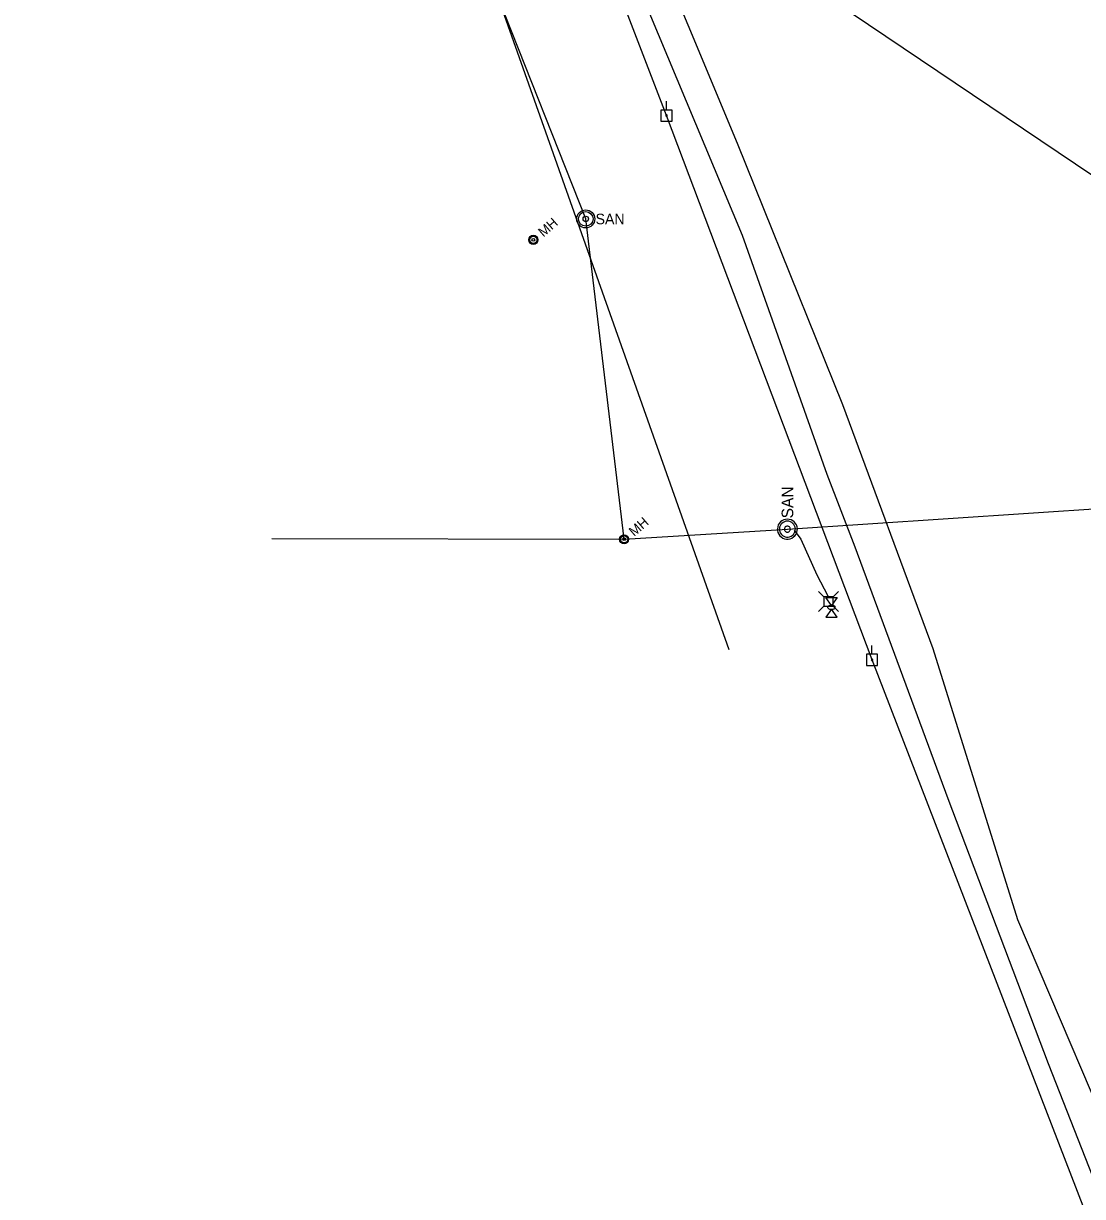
# Model space of a CAD drawing. Extents: x 596028 to 606371, y 330010 to 403088.
# Drawn here: x 602147.8 to 602498.3, y 353446.6 to 353834.8 of the extents above; entities that cross this region are included whole.
import ezdxf

# ---------------------------------------------------------------- set-up
doc = ezdxf.new("R2010")
doc.units = 0
for name, color, linetype in [('E_FTMS_Conduit', 7, 'Continuous'), ('E_UTL_E', 7, 'Continuous'), ('E_UTL_E_Bold', 7, 'Continuous'), ('E_UTL_E_UG', 7, 'Continuous'), ('E_UTL_EPowerPole', 7, 'Continuous'), ('E_UTL_FO_UG_QWEST', 7, 'Continuous'), ('E_UTL_G_UG', 7, 'Continuous'), ('E_UTL_Overhead', 7, 'Continuous'), ('E_UTL_SAN_MH', 7, 'Continuous'), ('E_UTL_SAN_UG', 7, 'Continuous'), ('E_UTL_SAN_UG_MMSD', 7, 'Continuous')]:
    doc.layers.add(name, color=color, linetype=linetype)

msp = doc.modelspace()

# ---------------------------------------------------------------- linework, layer by layer
at = {"layer": 'E_FTMS_Conduit'}
msp.add_lwpolyline([(602734.78, 352891.69), (602698.69, 352975.92), (602667.81, 353054.24), (602645.72, 353130.78), (602610.14, 353206.87), (602580.81, 353284.37), (602548.82, 353367.3), (602515.43, 353447.91), (602476.95, 353538.14), (602448.85, 353627.85), (602419.04, 353708.61), (602384.09, 353795.14), (602351.42, 353873.57), (602322.54, 353957.36), (602293.02, 354034.05), (602262.08, 354114.29), (602230.08, 354192.55), (602200.4, 354271.32)], dxfattribs=at)
at = {"layer": 'E_UTL_E'}
for points in [[(602412.72, 353645.06), (602410.97, 353646.82)], [(602415.81, 353645.06), (602417.57, 353646.82)], [(602415.81, 353645.06), (602412.72, 353645.06)], [(602412.72, 353645.06), (602412.72, 353641.97)], [(602415.81, 353641.97), (602415.81, 353645.06)], [(602412.72, 353641.97), (602410.97, 353640.22)], [(602412.72, 353641.97), (602415.81, 353641.97)], [(602415.81, 353641.97), (602417.57, 353640.22)]]:
    msp.add_lwpolyline(points, dxfattribs=at)
at = {"layer": 'E_UTL_E_Bold'}
for points in [[(602413.33, 353644.88), (602417.14, 353644.88)], [(602415.23, 353642.22), (602413.33, 353644.88)], [(602417.14, 353644.88), (602415.23, 353642.22)], [(602415.23, 353640.94), (602413.33, 353638.28)], [(602416.5, 353641.58), (602416.48, 353641.7), (602416.41, 353641.82), (602416.3, 353641.92), (602416.15, 353642.02), (602415.97, 353642.1), (602415.76, 353642.16), (602415.53, 353642.2), (602415.29, 353642.21), (602415.05, 353642.21), (602414.82, 353642.18), (602414.6, 353642.13), (602414.4, 353642.06), (602414.23, 353641.97), (602414.1, 353641.87), (602414.01, 353641.76), (602413.97, 353641.64), (602413.97, 353641.52), (602414.01, 353641.4), (602414.1, 353641.29), (602414.23, 353641.19), (602414.4, 353641.1), (602414.6, 353641.03), (602414.82, 353640.98), (602415.05, 353640.95), (602415.29, 353640.95), (602415.53, 353640.96), (602415.76, 353641), (602415.97, 353641.06), (602416.15, 353641.14), (602416.3, 353641.24), (602416.41, 353641.34), (602416.48, 353641.46), (602416.5, 353641.58)], [(602417.14, 353638.28), (602415.23, 353640.94)], [(602413.33, 353638.28), (602417.14, 353638.28)]]:
    msp.add_lwpolyline(points, dxfattribs=at)
at = {"layer": 'E_UTL_E_UG'}
msp.add_lwpolyline([(602402.9, 353667.16), (602405.14, 353664.19), (602410.4, 353652.32), (602414.04, 353645.38)], dxfattribs=at)
at = {"layer": 'E_UTL_EPowerPole'}
for points in [[(602362.47, 353806.17), (602358.78, 353806.17)], [(602358.78, 353806.17), (602358.78, 353802.48)], [(602360.63, 353806.17), (602360.63, 353809.08)], [(602362.47, 353802.48), (602362.47, 353806.17)], [(602358.78, 353802.48), (602362.47, 353802.48)], [(602360.9, 353804.33), (602360.89, 353804.38), (602360.88, 353804.42), (602360.86, 353804.46), (602360.83, 353804.49), (602360.8, 353804.52), (602360.76, 353804.55), (602360.71, 353804.56), (602360.67, 353804.57), (602360.62, 353804.57), (602360.58, 353804.56), (602360.54, 353804.54), (602360.5, 353804.51), (602360.47, 353804.48), (602360.45, 353804.44), (602360.43, 353804.4), (602360.42, 353804.35), (602360.42, 353804.31), (602360.43, 353804.26), (602360.45, 353804.22), (602360.47, 353804.18), (602360.5, 353804.15), (602360.54, 353804.12), (602360.58, 353804.1), (602360.62, 353804.09), (602360.67, 353804.09), (602360.71, 353804.1), (602360.76, 353804.11), (602360.8, 353804.14), (602360.83, 353804.17), (602360.86, 353804.2), (602360.88, 353804.24), (602360.89, 353804.29), (602360.9, 353804.33)], [(602428.64, 353626.04), (602428.64, 353628.95)], [(602430.48, 353626.04), (602426.79, 353626.04)], [(602426.79, 353626.04), (602426.79, 353622.35)], [(602428.91, 353624.2), (602428.9, 353624.24), (602428.89, 353624.28), (602428.87, 353624.32), (602428.84, 353624.36), (602428.81, 353624.39), (602428.77, 353624.41), (602428.72, 353624.43), (602428.68, 353624.43), (602428.63, 353624.43), (602428.59, 353624.42), (602428.55, 353624.4), (602428.51, 353624.38), (602428.48, 353624.34), (602428.46, 353624.3), (602428.44, 353624.26), (602428.43, 353624.22), (602428.43, 353624.17), (602428.44, 353624.13), (602428.46, 353624.09), (602428.48, 353624.05), (602428.51, 353624.02), (602428.55, 353623.99), (602428.59, 353623.97), (602428.63, 353623.96), (602428.68, 353623.96), (602428.72, 353623.96), (602428.77, 353623.98), (602428.81, 353624), (602428.84, 353624.03), (602428.87, 353624.07), (602428.89, 353624.11), (602428.9, 353624.15), (602428.91, 353624.2)], [(602430.48, 353622.35), (602430.48, 353626.04)], [(602426.79, 353622.35), (602430.48, 353622.35)]]:
    msp.add_lwpolyline(points, dxfattribs=at)
at = {"layer": 'E_UTL_FO_UG_QWEST'}
msp.add_lwpolyline([(602719.84, 352882.99), (602693.3, 352950.04), (602682.74, 352976.56), (602635.69, 353094.91), (602587.28, 353229.53), (602553.43, 353318.33), (602535.85, 353366.41), (602487.12, 353490.5), (602453.86, 353578.25), (602423.13, 353661.5), (602413.78, 353685.51), (602385.74, 353764.65), (602351.85, 353846.05), (602319.93, 353934.36), (602282.62, 354028.66), (602263.22, 354084.13), (602230.09, 354165.45), (602187.47, 354285.66)], dxfattribs=at)
at = {"layer": 'E_UTL_G_UG'}
for points in [[(602381.42, 353627.49), (602307.53, 353835.96), (602266.02, 353950.82), (602151.72, 354252.5), (602084.88, 354419.03)], [(602663.79, 353676.69), (602626.6, 353699.86), (602612.06, 353709.74), (602600.45, 353716.14), (602586.79, 353727.58), (602569.93, 353738.55), (602325.24, 353903.29), (602317.34, 353906.33), (602299.51, 353921.31), (602276.11, 353938.2), (602259.37, 353980.94), (602242.57, 354023.5), (602228.81, 354058.82), (602211.65, 354103.59), (602191.45, 354156.33), (602174.07, 354202.81), (602158.52, 354244.95)]]:
    msp.add_lwpolyline(points, dxfattribs=at)
at = {"layer": 'E_UTL_Overhead'}
msp.add_lwpolyline([(602786.89, 352671.3), (602719.9, 352862.04), (602644.85, 353058), (602574.25, 353244.39), (602502.81, 353432.28), (602428.67, 353624.2), (602360.66, 353804.33), (602303.82, 353952.18), (602250.37, 354092.88), (602197.72, 354232.78), (602144.03, 354374.9), (602091.31, 354515.03), (602040.95, 354648.65), (601976.43, 354817.48), (601911.13, 354985.41), (601846.94, 355153.54), (601811.73, 355320.66), (601775.11, 355493.17)], dxfattribs=at)
at = {"layer": 'E_UTL_SAN_MH'}
for points in [[(602400.65, 353670.76), (602400.02, 353670.7), (602399.42, 353670.53), (602398.86, 353670.24), (602398.37, 353669.85), (602397.96, 353669.38), (602397.64, 353668.84), (602397.44, 353668.24), (602397.35, 353667.62), (602397.38, 353666.99), (602397.53, 353666.39), (602397.79, 353665.81), (602398.15, 353665.3), (602398.61, 353664.87), (602399.13, 353664.53), (602399.72, 353664.3), (602400.33, 353664.18), (602400.96, 353664.18), (602401.58, 353664.3), (602402.16, 353664.53), (602402.69, 353664.87), (602403.14, 353665.3), (602403.5, 353665.81), (602403.76, 353666.39), (602403.91, 353666.99), (602403.94, 353667.62), (602403.85, 353668.24), (602403.65, 353668.84), (602403.33, 353669.38), (602402.92, 353669.85), (602402.43, 353670.24), (602401.87, 353670.53), (602401.27, 353670.7), (602400.65, 353670.76)], [(602400.65, 353670.1), (602400.15, 353670.06), (602399.66, 353669.92), (602399.22, 353669.69), (602398.82, 353669.38), (602398.5, 353669), (602398.24, 353668.56), (602398.08, 353668.09), (602398.01, 353667.59), (602398.03, 353667.09), (602398.15, 353666.6), (602398.36, 353666.14), (602398.65, 353665.74), (602399.01, 353665.39), (602399.44, 353665.12), (602399.9, 353664.93), (602400.4, 353664.84), (602400.9, 353664.84), (602401.39, 353664.93), (602401.86, 353665.12), (602402.28, 353665.39), (602402.64, 353665.74), (602402.93, 353666.14), (602403.14, 353666.6), (602403.26, 353667.09), (602403.28, 353667.59), (602403.21, 353668.09), (602403.05, 353668.56), (602402.8, 353669), (602402.47, 353669.38), (602402.07, 353669.69), (602401.63, 353669.92), (602401.15, 353670.06), (602400.65, 353670.1)], [(602400.65, 353668.45), (602400.46, 353668.44), (602400.28, 353668.38), (602400.11, 353668.3), (602399.96, 353668.18), (602399.84, 353668.04), (602399.75, 353667.88), (602399.68, 353667.7), (602399.66, 353667.51), (602399.67, 353667.32), (602399.71, 353667.14), (602399.79, 353666.97), (602399.9, 353666.82), (602400.03, 353666.69), (602400.19, 353666.58), (602400.37, 353666.51), (602400.55, 353666.48), (602400.74, 353666.48), (602400.92, 353666.51), (602401.1, 353666.58), (602401.26, 353666.69), (602401.39, 353666.82), (602401.5, 353666.97), (602401.58, 353667.14), (602401.63, 353667.32), (602401.63, 353667.51), (602401.61, 353667.7), (602401.55, 353667.88), (602401.45, 353668.04), (602401.33, 353668.18), (602401.18, 353668.3), (602401.01, 353668.38), (602400.83, 353668.44), (602400.65, 353668.45)]]:
    msp.add_lwpolyline(points, dxfattribs=at)
for centre, radius in [((602333.91, 353770.14), 3), ((602333.91, 353770.14), 2.4), ((602333.91, 353770.14), 0.9), ((602316.56, 353763.22), 1.5), ((602316.56, 353763.22), 1.2), ((602316.56, 353763.22), 0.45), ((602346.6, 353664.12), 1.5), ((602346.6, 353664.12), 1.2), ((602346.6, 353664.12), 0.45)]:
    msp.add_circle(centre, radius, dxfattribs=at)
at = {"layer": 'E_UTL_SAN_UG'}
for p, q in [((602333.91, 353770.14), (602249.61, 353983.6)), ((602346.6, 353664.12), (602333.91, 353770.14))]:
    msp.add_line(p, q, dxfattribs=at)
msp.add_lwpolyline([(602230.03, 353664.34), (602346.6, 353664.12)], dxfattribs=at)
at = {"layer": 'E_UTL_SAN_UG_MMSD'}
for p, q in [((602400.64, 353667.45), (602717.07, 353688.47)), ((602346.6, 353664.12), (602400.64, 353667.45))]:
    msp.add_line(p, q, dxfattribs=at)

# ---------------------------------------------------------------- texts
at = {"layer": 'E_UTL_SAN_MH'}
for s, height, rotation, p in [('MH', 3.24, 40.9335, (602319.89, 353763.96)), ('SAN', 3.849, 90, (602402.59, 353671.03)), ('MH', 3.24, 40.9335, (602349.93, 353664.86))]:
    msp.add_text(s, height=height, rotation=rotation, dxfattribs=at).set_placement(p)
msp.add_text('SAN', height=3.499, dxfattribs=at).set_placement((602337.15, 353768.37))

doc.saveas('drawing.dxf')
